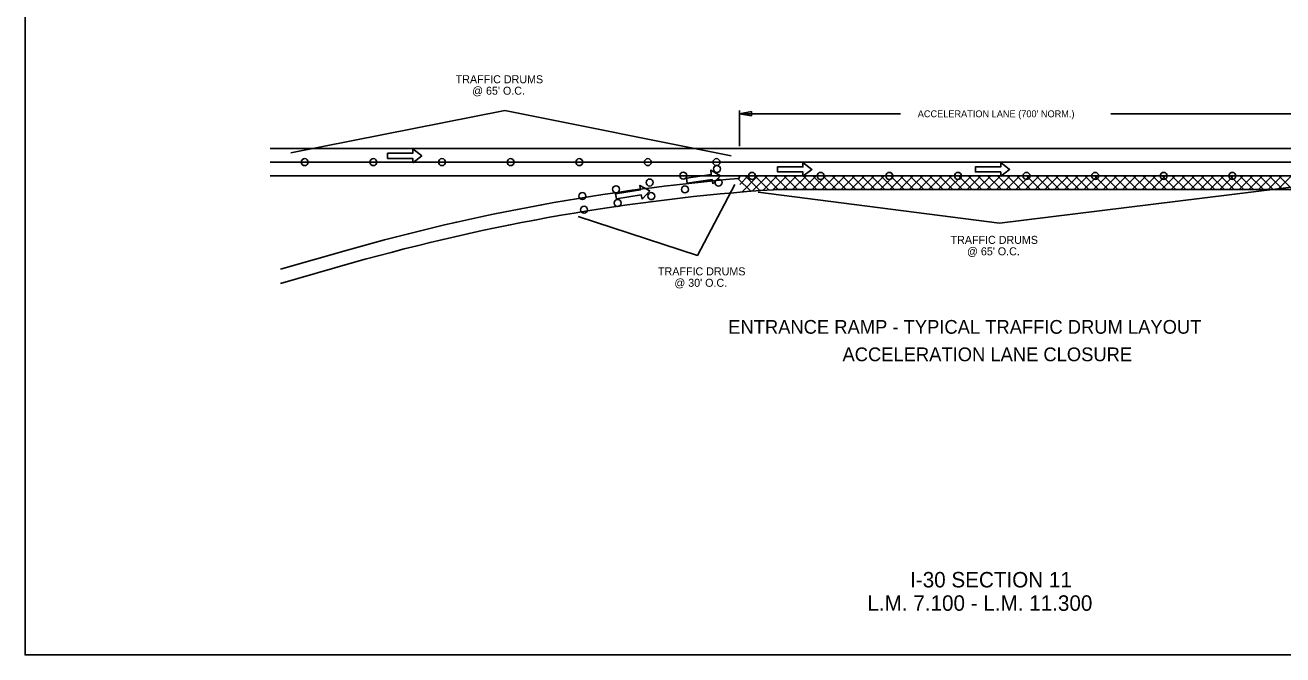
# Model space of a CAD drawing. Extents: x 1374027 to 1374537, y 380415 to 381405.
# Drawn here: x 1374367.1 to 1374477.1, y 380635.2 to 380690.2 of the extents above; entities that cross this region are included whole.
import ezdxf

# ---------------------------------------------------------------- set-up
doc = ezdxf.new("R2010")
doc.units = 0
for name, color, linetype in [('Default', 7, 'Continuous'), ('DSN_DRFT_Junk-No-Plot', 7, 'Continuous'), ('Edge of Lanes', 7, 'Continuous'), ('Level 1', 7, 'Continuous'), ('Level 40', 7, 'Continuous'), ('NOTES', 7, 'Continuous'), ('R_Border Notes', 7, 'Continuous')]:
    doc.layers.add(name, color=color, linetype=linetype)

msp = doc.modelspace()

# ---------------------------------------------------------------- linework, layer by layer
at = {"layer": 'Default'}
for points in [[(1374400.98, 380678.16), (1374401.76, 380678.76), (1374400.98, 380679.36), (1374400.98, 380678.99), (1374398.77, 380678.99), (1374398.77, 380678.54), (1374400.98, 380678.54)], [(1374427.2, 380676.32), (1374427.89, 380677.02), (1374427.03, 380677.5), (1374427.08, 380677.13), (1374424.9, 380676.82), (1374424.96, 380676.37), (1374427.15, 380676.69)], [(1374435.09, 380676.98), (1374435.87, 380677.58), (1374435.09, 380678.18), (1374435.09, 380677.8), (1374432.88, 380677.8), (1374432.88, 380677.35), (1374435.09, 380677.35)], [(1374452.38, 380676.98), (1374453.16, 380677.58), (1374452.38, 380678.18), (1374452.38, 380677.8), (1374450.17, 380677.8), (1374450.17, 380677.35), (1374452.38, 380677.35)], [(1374421.02, 380674.98), (1374421.69, 380675.7), (1374420.83, 380676.17), (1374420.89, 380675.8), (1374418.71, 380675.45), (1374418.78, 380675.01), (1374420.96, 380675.35)]]:
    msp.add_lwpolyline(points, close=True, dxfattribs=at)
at = {"layer": 'DSN_DRFT_Junk-No-Plot'}
for points in [[(1374367.08, 380745.17), (1374537.08, 380745.17), (1374537.08, 380635.17), (1374367.08, 380635.17)], [(1374367.08, 380745.17), (1374367.08, 380635.17), (1374537.08, 380635.17), (1374537.08, 380745.17)]]:
    msp.add_lwpolyline(points, close=True, dxfattribs=at)
at = {"layer": 'Edge of Lanes'}
for p, q in [((1374518.49, 380679.41), (1374388.51, 380679.41)), ((1374518.49, 380678.21), (1374388.51, 380678.21)), ((1374429.42, 380677.01), (1374388.51, 380677.01)), ((1374499.53, 380677.01), (1374429.42, 380677.01)), ((1374429.44, 380676.75), (1374430.53, 380675.66)), ((1374429.56, 380676.27), (1374430.3, 380677.01)), ((1374429.74, 380675.6), (1374431.15, 380677.01)), ((1374430.03, 380677.01), (1374431.32, 380675.72)), ((1374430.66, 380675.67), (1374432, 380677.01)), ((1374430.88, 380677.01), (1374432.11, 380675.78)), ((1374431.57, 380675.74), (1374432.85, 380677.01)), ((1374431.72, 380677.01), (1374432.92, 380675.81)), ((1374432.49, 380675.81), (1374433.69, 380677.01)), ((1374432.57, 380677.01), (1374433.77, 380675.81)), ((1374433.34, 380675.81), (1374434.54, 380677.01)), ((1374433.42, 380677.01), (1374434.62, 380675.81)), ((1374434.19, 380675.81), (1374435.39, 380677.01)), ((1374434.27, 380677.01), (1374435.47, 380675.81)), ((1374435.04, 380675.81), (1374436.24, 380677.01)), ((1374435.12, 380677.01), (1374436.32, 380675.81)), ((1374435.89, 380675.81), (1374437.09, 380677.01)), ((1374435.97, 380677.01), (1374437.17, 380675.81)), ((1374436.74, 380675.81), (1374437.94, 380677.01)), ((1374436.82, 380677.01), (1374438.02, 380675.81)), ((1374437.59, 380675.81), (1374438.79, 380677.01)), ((1374437.66, 380677.01), (1374438.86, 380675.81)), ((1374438.43, 380675.81), (1374439.63, 380677.01)), ((1374438.51, 380677.01), (1374439.71, 380675.81)), ((1374439.28, 380675.81), (1374440.48, 380677.01)), ((1374439.36, 380677.01), (1374440.56, 380675.81)), ((1374440.13, 380675.81), (1374441.33, 380677.01)), ((1374440.21, 380677.01), (1374441.41, 380675.81)), ((1374440.98, 380675.81), (1374442.18, 380677.01)), ((1374441.06, 380677.01), (1374442.26, 380675.81)), ((1374441.83, 380675.81), (1374443.03, 380677.01)), ((1374441.91, 380677.01), (1374443.11, 380675.81)), ((1374442.68, 380675.81), (1374443.88, 380677.01)), ((1374442.75, 380677.01), (1374443.95, 380675.81)), ((1374443.52, 380675.81), (1374444.72, 380677.01)), ((1374443.6, 380677.01), (1374444.8, 380675.81)), ((1374444.37, 380675.81), (1374445.57, 380677.01)), ((1374444.45, 380677.01), (1374445.65, 380675.81)), ((1374445.22, 380675.81), (1374446.42, 380677.01)), ((1374445.3, 380677.01), (1374446.5, 380675.81)), ((1374446.07, 380675.81), (1374447.27, 380677.01)), ((1374446.15, 380677.01), (1374447.35, 380675.81)), ((1374446.92, 380675.81), (1374448.12, 380677.01)), ((1374447, 380677.01), (1374448.2, 380675.81)), ((1374447.77, 380675.81), (1374448.97, 380677.01)), ((1374447.85, 380677.01), (1374449.05, 380675.81)), ((1374448.62, 380675.81), (1374449.82, 380677.01)), ((1374448.69, 380677.01), (1374449.89, 380675.81)), ((1374449.46, 380675.81), (1374450.66, 380677.01)), ((1374449.54, 380677.01), (1374450.74, 380675.81)), ((1374450.31, 380675.81), (1374451.51, 380677.01)), ((1374450.39, 380677.01), (1374451.59, 380675.81)), ((1374451.16, 380675.81), (1374452.36, 380677.01)), ((1374451.24, 380677.01), (1374452.44, 380675.81)), ((1374452.01, 380675.81), (1374453.21, 380677.01)), ((1374452.09, 380677.01), (1374453.29, 380675.81)), ((1374452.86, 380675.81), (1374454.06, 380677.01)), ((1374452.94, 380677.01), (1374454.14, 380675.81)), ((1374453.71, 380675.81), (1374454.91, 380677.01)), ((1374453.79, 380677.01), (1374454.99, 380675.81)), ((1374454.56, 380675.81), (1374455.76, 380677.01)), ((1374454.63, 380677.01), (1374455.83, 380675.81)), ((1374455.4, 380675.81), (1374456.6, 380677.01)), ((1374455.48, 380677.01), (1374456.68, 380675.81)), ((1374456.25, 380675.81), (1374457.45, 380677.01)), ((1374456.33, 380677.01), (1374457.53, 380675.81)), ((1374457.1, 380675.81), (1374458.3, 380677.01)), ((1374457.18, 380677.01), (1374458.38, 380675.81)), ((1374457.95, 380675.81), (1374459.15, 380677.01)), ((1374458.03, 380677.01), (1374459.23, 380675.81)), ((1374458.8, 380675.81), (1374460, 380677.01)), ((1374458.88, 380677.01), (1374460.08, 380675.81)), ((1374459.65, 380675.81), (1374460.85, 380677.01)), ((1374459.73, 380677.01), (1374460.93, 380675.81)), ((1374460.5, 380675.81), (1374461.7, 380677.01)), ((1374460.57, 380677.01), (1374461.77, 380675.81)), ((1374461.34, 380675.81), (1374462.54, 380677.01)), ((1374461.42, 380677.01), (1374462.62, 380675.81)), ((1374462.19, 380675.81), (1374463.39, 380677.01)), ((1374462.27, 380677.01), (1374463.47, 380675.81)), ((1374463.04, 380675.81), (1374464.24, 380677.01)), ((1374463.12, 380677.01), (1374464.32, 380675.81)), ((1374463.89, 380675.81), (1374465.09, 380677.01)), ((1374463.97, 380677.01), (1374465.17, 380675.81)), ((1374464.74, 380675.81), (1374465.94, 380677.01)), ((1374464.82, 380677.01), (1374466.02, 380675.81)), ((1374465.59, 380675.81), (1374466.79, 380677.01)), ((1374465.67, 380677.01), (1374466.87, 380675.81)), ((1374466.43, 380675.81), (1374467.63, 380677.01)), ((1374466.51, 380677.01), (1374467.71, 380675.81)), ((1374467.28, 380675.81), (1374468.48, 380677.01)), ((1374467.36, 380677.01), (1374468.56, 380675.81)), ((1374468.13, 380675.81), (1374469.33, 380677.01)), ((1374468.21, 380677.01), (1374469.41, 380675.81)), ((1374468.98, 380675.81), (1374470.18, 380677.01)), ((1374469.06, 380677.01), (1374470.26, 380675.81)), ((1374469.83, 380675.81), (1374471.03, 380677.01)), ((1374469.91, 380677.01), (1374471.11, 380675.81)), ((1374470.68, 380675.81), (1374471.88, 380677.01)), ((1374470.76, 380677.01), (1374471.96, 380675.81)), ((1374471.53, 380675.81), (1374472.73, 380677.01)), ((1374471.6, 380677.01), (1374472.8, 380675.81)), ((1374472.37, 380675.81), (1374473.57, 380677.01)), ((1374472.45, 380677.01), (1374473.65, 380675.81)), ((1374473.22, 380675.81), (1374474.42, 380677.01)), ((1374473.3, 380677.01), (1374474.5, 380675.81)), ((1374474.07, 380675.81), (1374475.27, 380677.01)), ((1374474.15, 380677.01), (1374475.35, 380675.81)), ((1374474.92, 380675.81), (1374476.12, 380677.01)), ((1374475, 380677.01), (1374476.2, 380675.81)), ((1374475.77, 380675.81), (1374476.97, 380677.01)), ((1374475.85, 380677.01), (1374477.05, 380675.81)), ((1374476.62, 380675.81), (1374477.82, 380677.01)), ((1374476.7, 380677.01), (1374477.9, 380675.81)), ((1374499.53, 380675.81), (1374432.52, 380675.81)), ((1374389.42, 380668.85), (1374395.36, 380670.56)), ((1374389.42, 380667.6), (1374395.69, 380669.41))]:
    msp.add_line(p, q, dxfattribs=at)
for centre, radius, start, end in [((1374444.56, 380497.35), 180.06, 94.8177, 105.8571), ((1374429.42, 380676.89), 0.116, 278.872, 86.6139), ((1374444.56, 380497.35), 178.86, 93.859, 105.8563)]:
    msp.add_arc(centre, radius, start, end, dxfattribs=at)
at = {"layer": 'Level 1'}
for points in [[(1374390.31, 380679.02), (1374409.02, 380682.72), (1374428.82, 380678.77)], [(1374415.43, 380673.45), (1374425.86, 380670.06), (1374429.14, 380676.25)], [(1374431.17, 380675.58), (1374452.28, 380672.89), (1374478.97, 380676.16)]]:
    msp.add_lwpolyline(points, dxfattribs=at)
at = {"layer": 'Level 40'}
for centre in [(1374391.53, 380678.21), (1374397.53, 380678.21), (1374403.53, 380678.21), (1374409.53, 380678.21), (1374415.53, 380678.21), (1374421.53, 380678.21), (1374427.53, 380678.21), (1374427.57, 380677.62), (1374421.69, 380676.43), (1374424.63, 380677.03), (1374427.71, 380676.42), (1374430.64, 380677.01), (1374436.64, 380677.01), (1374442.64, 380677.01), (1374448.64, 380677.01), (1374454.64, 380677.01), (1374460.64, 380677.01), (1374466.64, 380677.01), (1374472.64, 380677.01), (1374415.81, 380675.25), (1374418.75, 380675.84), (1374421.83, 380675.24), (1374424.77, 380675.83), (1374415.95, 380674.05), (1374418.89, 380674.64)]:
    msp.add_circle(centre, 0.305, dxfattribs=at)
at = {"layer": 'NOTES'}
for p, q in [((1374429.53, 380679.61), (1374429.53, 380682.73)), ((1374443.61, 380682.43), (1374429.53, 380682.43)), ((1374462.01, 380682.43), (1374479.53, 380682.43))]:
    msp.add_line(p, q, dxfattribs=at)
msp.add_lwpolyline([(1374430.58, 380682.25), (1374429.53, 380682.43), (1374430.58, 380682.62)], close=True, dxfattribs=at)

# ---------------------------------------------------------------- texts
at = {"layer": 'Level 1'}
for s, height, p in [('TRAFFIC DRUMS', 0.7, (1374404.73, 380685.1)), ("@ 65' O.C.", 0.7, (1374406.17, 380684.1)), ('TRAFFIC DRUMS', 0.7, (1374448, 380671.07)), ("@ 65' O.C.", 0.7, (1374449.44, 380670.07)), ('TRAFFIC DRUMS', 0.7, (1374422.42, 380668.32)), ("@ 30' O.C.", 0.7, (1374423.85, 380667.32)), ('ENTRANCE RAMP - TYPICAL TRAFFIC DRUM LAYOUT', 1.2, (1374428.56, 380663.22)), ('ACCELERATION LANE CLOSURE', 1.2, (1374438.55, 380660.82))]:
    msp.add_text(s, height=height, rotation=360, dxfattribs=at).set_placement(p)
at = {"layer": 'NOTES'}
msp.add_text("ACCELERATION LANE (700' NORM.)", height=0.6, dxfattribs=at).set_placement((1374445.13, 380682.13))
at = {"layer": 'R_Border Notes'}
for s, p in [('I-30 SECTION 11', (1374444.46, 380641.06)), ('L.M. 7.100 - L.M. 11.300', (1374440.73, 380639.02))]:
    msp.add_text(s, height=1.35, dxfattribs=at).set_placement(p)

doc.saveas('drawing.dxf')
